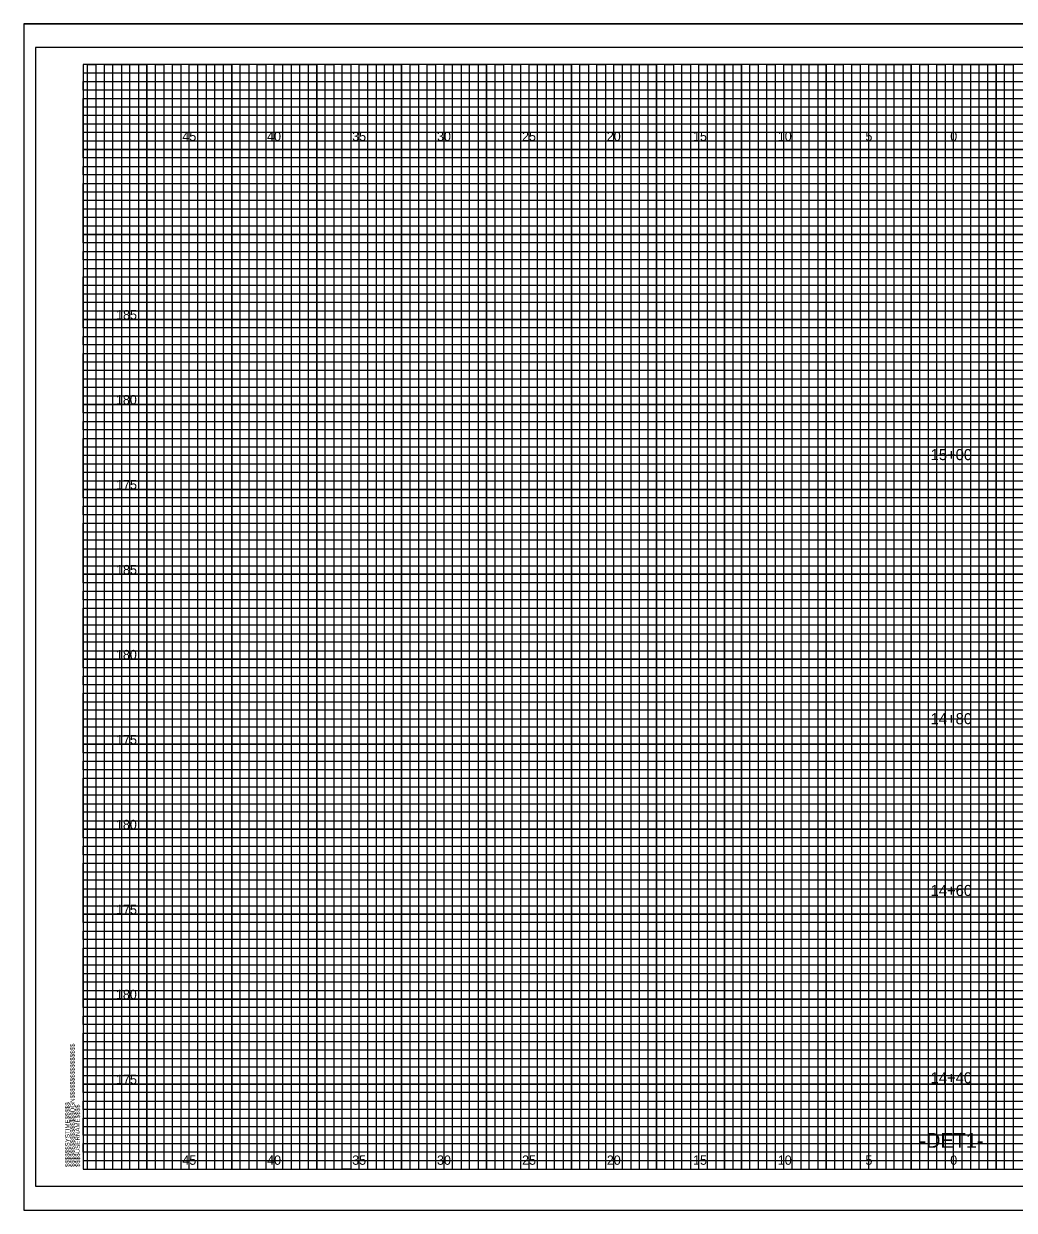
# Model space of a CAD drawing. Extents: x -4 to 103, y -2 to 280.
# Drawn here: x -3.5 to 54.8, y 139.2 to 209.1 of the extents above; entities that cross this region are included whole.
import ezdxf

# ---------------------------------------------------------------- set-up
doc = ezdxf.new("R2010")
doc.units = 0
for name, color, linetype in [('Exist XS Center Line Elevation Label', 7, 'Continuous'), ('Old_Level_63', 7, 'Continuous'), ('Prop XS Dump Level', 7, 'Continuous'), ('Prop XS EOT Tick Mark', 7, 'Continuous'), ('Prop XS Finish Grade Earthwork', 7, 'Continuous'), ('Prop XS Pvmt Edge Slope', 7, 'Continuous'), ('Prop XS SE Text', 7, 'Continuous'), ('Prop XS Subgrade Earthwork', 7, 'Continuous'), ('Sheet Cutting Line CELL', 7, 'Continuous'), ('Sheet Plot Border Inside CELL', 7, 'Continuous'), ('Sheet Plot Border Outside CELL', 7, 'Continuous')]:
    doc.layers.add(name, color=color, linetype=linetype)

msp = doc.modelspace()

# ---------------------------------------------------------------- linework, layer by layer
at = {"layer": 'Exist XS Center Line Elevation Label'}
for points in [[(1.25, 141.65), (1.25, 206.65), (3.75, 206.65), (3.75, 141.65), (6.25, 141.65), (6.25, 206.65), (8.75, 206.65), (8.75, 141.65), (11.25, 141.65), (11.25, 206.65), (13.75, 206.65), (13.75, 141.65), (16.25, 141.65), (16.25, 206.65), (18.75, 206.65), (18.75, 141.65), (21.25, 141.65), (21.25, 206.65), (23.75, 206.65), (23.75, 141.65), (26.25, 141.65), (26.25, 206.65), (28.75, 206.65), (28.75, 141.65), (31.25, 141.65), (31.25, 206.65), (33.75, 206.65), (33.75, 141.65), (36.25, 141.65), (36.25, 206.65), (38.75, 206.65), (38.75, 141.65), (41.25, 141.65), (41.25, 206.65), (43.75, 206.65), (43.75, 141.65), (46.25, 141.65), (46.25, 206.65), (48.75, 206.65), (48.75, 141.65), (51.25, 141.65), (51.25, 206.65), (53.75, 206.65), (53.75, 141.65)], [(102.5, 201.65), (0, 201.65), (0, 204.15), (74.25, 204.15)], [(102.5, 196.65), (0, 196.65), (0, 199.15), (102.5, 199.15)], [(102.5, 191.65), (0, 191.65), (0, 194.15), (102.5, 194.15)], [(102.5, 186.65), (0, 186.65), (0, 189.15), (102.5, 189.15)], [(102.5, 181.65), (0, 181.65), (0, 184.15), (102.5, 184.15)], [(102.5, 176.65), (0, 176.65), (0, 179.15), (102.5, 179.15)], [(102.5, 171.65), (0, 171.65), (0, 174.15), (102.5, 174.15)], [(102.5, 166.65), (0, 166.65), (0, 169.15), (102.5, 169.15)], [(102.5, 161.65), (0, 161.65), (0, 164.15), (102.5, 164.15)], [(102.5, 156.65), (0, 156.65), (0, 159.15), (102.5, 159.15)], [(102.5, 151.65), (0, 151.65), (0, 154.15), (102.5, 154.15)], [(102.5, 146.65), (0, 146.65), (0, 149.15), (102.5, 149.15)], [(0, 144.15), (102.5, 144.15)]]:
    msp.add_lwpolyline(points, dxfattribs=at)
at = {"layer": 'Old_Level_63'}
msp.add_lwpolyline([(102.5, 206.65), (0, 206.65), (0, 141.65), (102.5, 141.65)], close=True, dxfattribs=at)
at = {"layer": 'Prop XS Dump Level'}
for p, q in [((1.25, 141.65), (1.25, 206.65)), ((3.75, 141.65), (3.75, 206.65)), ((6.25, 141.65), (6.25, 206.65)), ((8.75, 141.65), (8.75, 206.65)), ((11.25, 141.65), (11.25, 206.65)), ((13.75, 141.65), (13.75, 206.65)), ((16.25, 141.65), (16.25, 206.65)), ((18.75, 141.65), (18.75, 206.65)), ((21.25, 141.65), (21.25, 206.65)), ((23.75, 141.65), (23.75, 206.65)), ((26.25, 141.65), (26.25, 206.65)), ((28.75, 141.65), (28.75, 206.65)), ((31.25, 141.65), (31.25, 206.65)), ((33.75, 141.65), (33.75, 206.65)), ((36.25, 141.65), (36.25, 206.65)), ((38.75, 141.65), (38.75, 206.65)), ((41.25, 141.65), (41.25, 206.65)), ((43.75, 141.65), (43.75, 206.65)), ((46.25, 141.65), (46.25, 206.65)), ((48.75, 141.65), (48.75, 206.65)), ((51.25, 141.65), (51.25, 206.65)), ((53.75, 141.65), (53.75, 206.65)), ((0, 204.15), (74.25, 204.15)), ((0, 201.65), (102.5, 201.65)), ((0, 199.15), (102.5, 199.15)), ((0, 196.65), (102.5, 196.65)), ((0, 194.15), (102.5, 194.15)), ((0, 191.65), (102.5, 191.65)), ((0, 189.15), (102.5, 189.15)), ((0, 186.65), (102.5, 186.65)), ((0, 184.15), (102.5, 184.15)), ((0, 181.65), (102.5, 181.65)), ((0, 179.15), (102.5, 179.15)), ((0, 176.65), (102.5, 176.65)), ((0, 174.15), (102.5, 174.15)), ((0, 171.65), (102.5, 171.65)), ((0, 169.15), (102.5, 169.15)), ((0, 166.65), (102.5, 166.65)), ((0, 164.15), (102.5, 164.15)), ((0, 161.65), (102.5, 161.65)), ((0, 159.15), (102.5, 159.15)), ((0, 156.65), (102.5, 156.65)), ((0, 154.15), (102.5, 154.15)), ((0, 151.65), (102.5, 151.65)), ((0, 149.15), (102.5, 149.15)), ((0, 146.65), (102.5, 146.65)), ((0, 144.15), (102.5, 144.15))]:
    msp.add_line(p, q, dxfattribs=at)
at = {"layer": 'Prop XS SE Text'}
for points in [[(0, 203.65), (0, 204.65), (74.25, 204.65), (74.25, 205.15), (0, 205.15), (0, 205.65), (74.25, 205.65), (74.25, 206.15), (0, 206.15)], [(0.25, 141.65), (0.25, 206.65), (0.75, 206.65), (0.75, 141.65), (1.75, 141.65), (1.75, 206.65), (2.25, 206.65), (2.25, 141.65), (2.75, 141.65), (2.75, 206.65), (3.25, 206.65), (3.25, 141.65), (4.25, 141.65), (4.25, 206.65), (4.75, 206.65), (4.75, 141.65), (5.25, 141.65), (5.25, 206.65), (5.75, 206.65), (5.75, 141.65), (6.75, 141.65), (6.75, 206.65), (7.25, 206.65), (7.25, 141.65), (7.75, 141.65), (7.75, 206.65), (8.25, 206.65), (8.25, 141.65), (9.25, 141.65), (9.25, 206.65), (9.75, 206.65), (9.75, 141.65), (10.25, 141.65), (10.25, 206.65), (10.75, 206.65), (10.75, 141.65), (11.75, 141.65), (11.75, 206.65), (12.25, 206.65), (12.25, 141.65), (12.75, 141.65), (12.75, 206.65), (13.25, 206.65), (13.25, 141.65), (14.25, 141.65), (14.25, 206.65), (14.75, 206.65), (14.75, 141.65), (15.75, 141.65), (15.25, 141.65), (15.25, 206.65), (15.75, 206.65), (15.75, 141.65), (16.75, 141.65), (16.75, 206.65), (17.25, 206.65), (17.25, 141.65), (17.75, 141.65), (17.75, 206.65), (18.25, 206.65), (18.25, 141.65), (19.25, 141.65), (19.25, 206.65), (19.75, 206.65), (19.75, 141.65), (20.25, 141.65), (20.25, 206.65), (20.75, 206.65), (20.75, 141.65), (21.75, 141.65), (21.75, 206.65), (22.25, 206.65), (22.25, 141.65), (22.75, 141.65), (22.75, 206.65), (23.25, 206.65), (23.25, 141.65), (24.25, 141.65), (24.25, 206.65), (24.75, 206.65), (24.75, 141.65), (25.25, 141.65), (25.25, 206.65), (25.75, 206.65), (25.75, 141.65), (26.75, 141.65), (26.75, 206.65), (27.25, 206.65), (27.25, 141.65), (27.75, 141.65), (27.75, 206.65), (28.25, 206.65), (28.25, 141.65), (29.25, 141.65), (29.25, 206.65), (29.75, 206.65), (29.75, 141.65), (30.25, 141.65), (30.25, 206.65), (30.75, 206.65), (30.75, 141.65)], [(30.75, 141.65), (31.75, 141.65), (31.75, 206.65), (32.25, 206.65), (32.25, 141.65), (32.75, 141.65), (32.75, 206.65), (33.25, 206.65), (33.25, 141.65), (34.25, 141.65), (34.25, 206.65), (34.75, 206.65), (34.75, 141.65), (35.25, 141.65), (35.25, 206.65), (35.75, 206.65), (35.75, 141.65), (36.75, 141.65), (36.75, 206.65), (37.25, 206.65), (37.25, 141.65), (37.75, 141.65), (37.75, 206.65), (37.75, 141.65)], [(38.25, 206.65), (38.25, 141.65), (39.25, 141.65), (39.25, 206.65), (39.75, 206.65), (39.75, 141.65), (40.25, 141.65), (40.25, 206.65), (40.75, 206.65), (40.75, 141.65), (41.75, 141.65), (41.75, 206.65), (42.25, 206.65), (42.25, 141.65), (42.75, 141.65), (42.75, 206.65), (43.25, 206.65), (43.25, 141.65), (43.75, 141.65), (44.25, 141.65), (44.25, 206.65), (44.75, 206.65), (44.75, 141.65), (45.25, 141.65), (45.25, 206.65), (45.75, 206.65), (45.75, 141.65), (46.75, 141.65), (46.75, 206.65), (47.25, 206.65), (47.25, 141.65), (47.75, 141.65), (47.75, 206.65), (48.25, 206.65), (48.25, 141.65), (49.25, 141.65), (49.25, 206.65), (49.75, 206.65), (49.75, 141.65), (50.25, 141.65), (50.25, 206.65), (50.75, 206.65), (50.75, 141.65), (51.75, 141.65), (51.75, 206.65), (52.25, 206.65), (52.25, 141.65), (52.75, 141.65), (52.75, 206.65), (53.25, 206.65), (53.25, 141.65), (54.25, 141.65), (54.25, 206.65), (54.75, 206.65), (54.75, 141.65), (55.25, 141.65)], [(102.5, 203.65), (0, 203.65)], [(102.5, 202.65), (0, 202.65), (0, 203.15), (102.5, 203.15)], [(102.5, 201.15), (0, 201.15), (0, 202.15), (102.5, 202.15)], [(102.5, 200.15), (0, 200.15), (0, 200.65), (102.5, 200.65)], [(102.5, 198.65), (0, 198.65), (0, 199.65), (102.5, 199.65)], [(102.5, 197.65), (0, 197.65), (0, 198.15), (102.5, 198.15)], [(102.5, 196.15), (0, 196.15), (0, 197.15), (102.5, 197.15)], [(102.5, 195.15), (0, 195.15), (0, 195.65), (102.5, 195.65)], [(0, 194.65), (102.5, 194.65)], [(102.5, 193.65), (0, 193.65)], [(102.5, 192.65), (0, 192.65), (0, 193.15), (102.5, 193.15)], [(102.5, 191.15), (0, 191.15), (0, 192.15), (102.5, 192.15)], [(102.5, 190.15), (0, 190.15), (0, 190.65), (102.5, 190.65)], [(102.5, 188.65), (0, 188.65), (0, 189.65), (102.5, 189.65)], [(102.5, 187.65), (0, 187.65), (0, 188.15), (102.5, 188.15)], [(102.5, 186.15), (0, 186.15), (0, 187.15), (102.5, 187.15)], [(102.5, 185.15), (0, 185.15), (0, 185.65), (102.5, 185.65)], [(102.5, 183.65), (0, 183.65), (0, 184.65), (102.5, 184.65)], [(102.5, 182.65), (0, 182.65), (0, 183.15), (102.5, 183.15)], [(102.5, 181.15), (0, 181.15), (0, 182.15), (102.5, 182.15)], [(102.5, 180.15), (0, 180.15), (0, 180.65), (102.5, 180.65)], [(102.5, 178.65), (0, 178.65), (0, 179.65), (102.5, 179.65)], [(102.5, 177.65), (0, 177.65), (0, 178.15), (102.5, 178.15)], [(102.5, 176.15), (0, 176.15), (0, 177.15), (102.5, 177.15)], [(102.5, 175.15), (0, 175.15), (0, 175.65), (102.5, 175.65)], [(102.5, 173.65), (0, 173.65), (0, 174.65), (102.5, 174.65)], [(102.5, 172.65), (0, 172.65), (0, 173.15)], [(0, 173.15), (102.5, 173.15)], [(102.5, 171.15), (0, 171.15), (0, 172.15), (102.5, 172.15)], [(102.5, 170.15), (0, 170.15), (0, 170.65), (102.5, 170.65)], [(102.5, 168.65), (0, 168.65), (0, 169.65), (102.5, 169.65)], [(102.5, 167.65), (0, 167.65), (0, 168.15), (102.5, 168.15)], [(102.5, 166.15), (0, 166.15), (0, 167.15), (102.5, 167.15)], [(102.5, 165.15), (0, 165.15), (0, 165.65), (102.5, 165.65)], [(102.5, 163.65), (0, 163.65), (0, 164.65), (102.5, 164.65)], [(102.5, 162.65), (0, 162.65), (0, 163.15), (102.5, 163.15)], [(102.5, 161.15), (0, 161.15), (0, 162.15), (102.5, 162.15)], [(102.5, 160.15), (0, 160.15), (0, 160.65), (102.5, 160.65)], [(102.5, 158.65), (0, 158.65), (0, 159.65), (102.5, 159.65)], [(102.5, 157.65), (0, 157.65), (0, 158.15), (102.5, 158.15)], [(102.5, 156.15), (0, 156.15), (0, 157.15), (102.5, 157.15)], [(102.5, 155.15), (0, 155.15), (0, 155.65), (102.5, 155.65)], [(102.5, 153.65), (0, 153.65), (0, 154.65), (102.5, 154.65)], [(102.5, 152.65), (0, 152.65), (0, 153.15), (102.5, 153.15)], [(102.5, 151.15), (0, 151.15), (0, 152.15), (102.5, 152.15)], [(102.5, 150.15), (0, 150.15), (0, 150.65), (102.5, 150.65)], [(102.5, 148.65), (0, 148.65), (0, 149.65), (102.5, 149.65)], [(102.5, 147.65), (0, 147.65), (0, 148.15), (102.5, 148.15)], [(102.5, 146.15), (0, 146.15), (0, 147.15), (102.5, 147.15)], [(102.5, 145.15), (0, 145.15), (0, 145.65), (102.5, 145.65)], [(102.5, 143.65), (0, 143.65), (0, 144.65), (102.5, 144.65)], [(102.5, 142.65), (0, 142.65), (0, 143.15), (102.5, 143.15)], [(0, 142.15), (102.5, 142.15)]]:
    msp.add_lwpolyline(points, dxfattribs=at)
at = {"layer": 'Sheet Cutting Line CELL'}
for p, q in [((-3.5, 209.05), (103.4, 209.05)), ((-3.5, 209.05), (-3.5, 139.225)), ((-3.5, 139.225), (103.4, 139.225))]:
    msp.add_line(p, q, dxfattribs=at)
at = {"layer": 'Sheet Plot Border Inside CELL'}
msp.add_lwpolyline([(103, 207.65), (-2.8, 207.65), (-2.8, 140.65), (103, 140.65)], close=True, dxfattribs=at)
at = {"layer": 'Sheet Plot Border Outside CELL'}
msp.add_lwpolyline([(103.4, 209.05), (-3.5, 209.05), (-3.5, 139.225), (103.4, 139.225)], close=True, dxfattribs=at)

# ---------------------------------------------------------------- texts
at = {"layer": 'Exist XS Center Line Elevation Label'}
msp.add_text('040397', height=0.0025, rotation=90, dxfattribs=at).set_placement((-0.001, 206.636))
at = {"layer": 'Old_Level_63'}
for s, p in [('$$$$$$$$$$$$$$$$DGN$$$$$$$$$$$$$$$$', (-0.5, 141.775)), ('$$$$$$SYSTIME$$$$$', (-0.797, 141.775)), ('$$$$USERNAME$$$$', (-0.2, 141.775))]:
    msp.add_text(s, height=0.2625, rotation=90, dxfattribs=at).set_placement(p)
at = {"layer": 'Prop XS EOT Tick Mark'}
for s, p in [('15+00', (49.893, 183.369)), ('14+80', (49.893, 167.829)), ('14+60', (49.893, 157.719)), ('14+40', (49.893, 146.695))]:
    msp.add_text(s, height=0.65, dxfattribs=at).set_placement(p)
at = {"layer": 'Prop XS Finish Grade Earthwork'}
msp.add_text('-DET1-', height=0.875, dxfattribs=at).set_placement((49.238, 142.9))
at = {"layer": 'Prop XS Pvmt Edge Slope'}
for s, p in [('45', (5.84, 202.15)), ('40', (10.831, 202.15)), ('35', (15.84, 202.15)), ('30', (20.831, 202.15)), ('25', (25.84, 202.15)), ('20', (30.831, 202.15)), ('15', (35.906, 202.15)), ('10', (40.897, 202.15)), ('5', (46.057, 202.15)), ('0', (51.049, 202.15)), ('0', (51.049, 202.15)), ('45', (5.84, 141.9)), ('40', (10.831, 141.9)), ('35', (15.84, 141.9)), ('30', (20.831, 141.9)), ('25', (25.84, 141.9)), ('20', (30.831, 141.9)), ('15', (35.906, 141.9)), ('10', (40.897, 141.9)), ('5', (46.057, 141.9)), ('0', (51.049, 141.9)), ('0', (51.049, 141.9))]:
    msp.add_text(s, height=0.55, dxfattribs=at).set_placement(p)
at = {"layer": 'Prop XS Subgrade Earthwork'}
for s, p in [('185', (1.938, 191.65)), ('180', (1.93, 186.65)), ('175', (1.938, 181.65)), ('185', (1.938, 176.65)), ('180', (1.93, 171.65)), ('175', (1.938, 166.65)), ('180', (1.93, 161.65)), ('175', (1.938, 156.65)), ('180', (1.93, 151.65)), ('175', (1.938, 146.65))]:
    msp.add_text(s, height=0.55, dxfattribs=at).set_placement(p)

doc.saveas('drawing.dxf')
